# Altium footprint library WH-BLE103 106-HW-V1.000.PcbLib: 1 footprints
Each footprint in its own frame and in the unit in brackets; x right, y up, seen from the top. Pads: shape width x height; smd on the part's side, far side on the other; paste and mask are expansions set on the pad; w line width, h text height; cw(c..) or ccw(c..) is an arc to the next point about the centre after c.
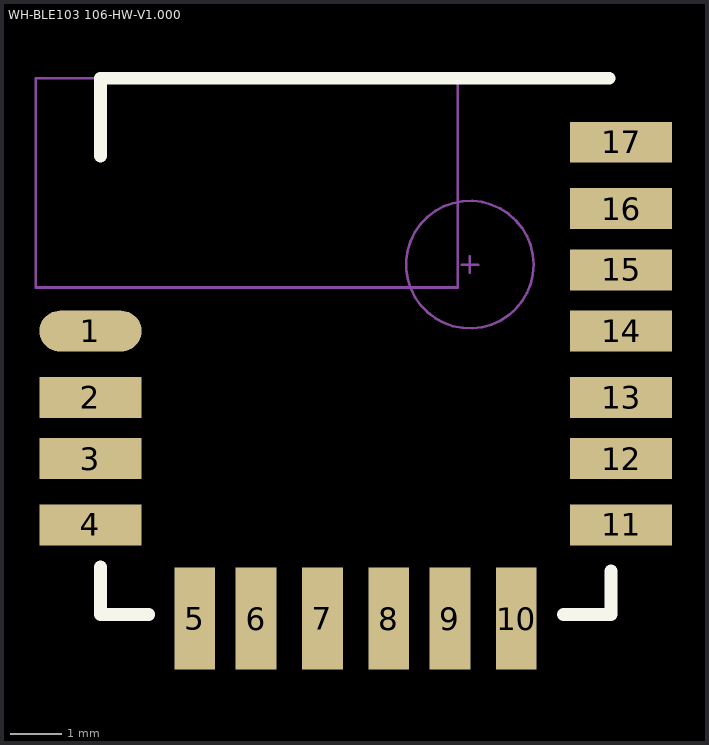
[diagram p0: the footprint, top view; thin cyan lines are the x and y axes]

## WH-BLE103 106-HW-V1.000 [mm]
pads (17):
  oval 2x0.8 smd: 1(-351.99,-838.996)
  rect 2x0.8 smd: 2(-351.99,-840.296) 3(-351.99,-841.496) 4(-351.99,-842.796) 11(-341.59,-842.796) 12(-341.59,-841.496) 13(-341.59,-840.296) 14(-341.59,-838.996) 15(-341.59,-837.796) 16(-341.59,-836.596) 17(-341.59,-835.296)
  rect 0.8x2 smd: 5(-349.944,-844.632) 6(-348.744,-844.632) 7(-347.444,-844.632) 8(-346.144,-844.632) 9(-344.944,-844.632) 10(-343.644,-844.632)
Top Overlay:
  lines w0.254: -351.79,-843.621 -351.79,-844.55 -350.847,-844.55 ; -351.79,-835.567 -351.79,-834.042 -341.83,-834.042 ; -342.719,-844.55 -341.79,-844.55 -341.79,-843.695
Mechanical 5:
  circle w0.051: c-344.555,-837.693 r1.25
  lines w0.051: -344.715,-837.693 -344.555,-837.693 ; -344.555,-837.853 -344.555,-837.693 ; -344.555,-837.533 -344.555,-837.693 ; -344.395,-837.693 -344.555,-837.693 ; -353.06,-838.142 -353.06,-834.042 -344.79,-834.042 -344.79,-838.142 -353.06,-838.142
